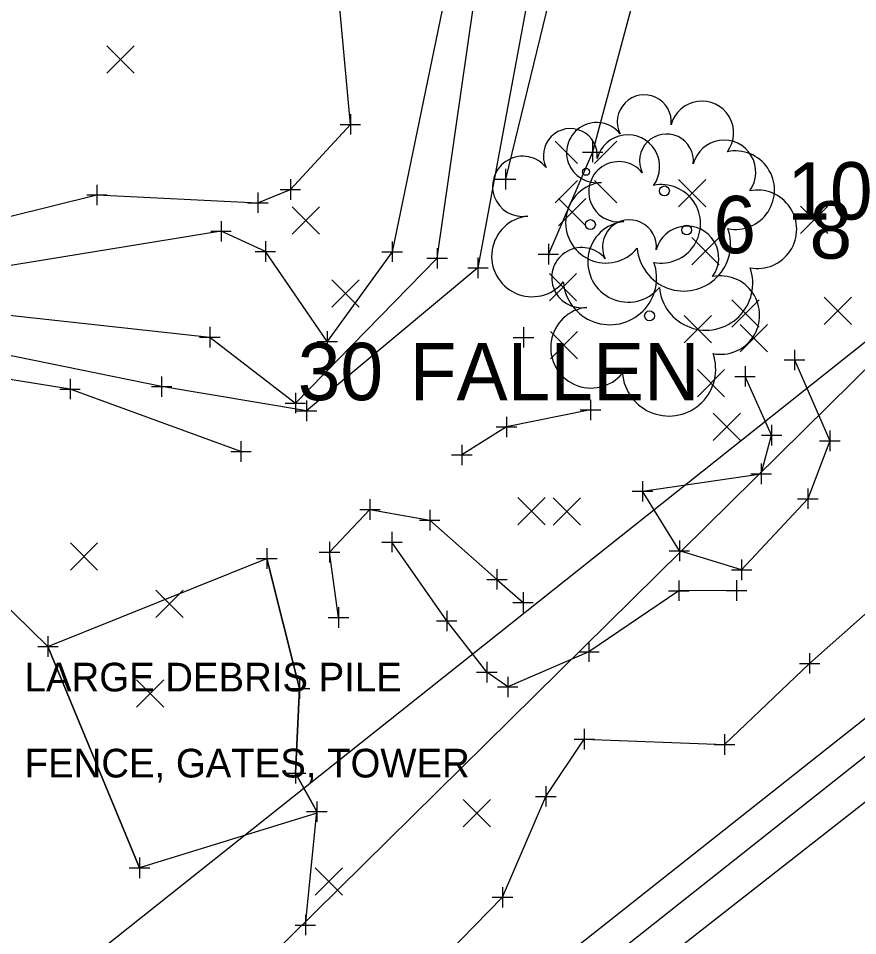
# Model space of a CAD drawing. Extents: x 2184635 to 2185378, y 369880 to 370486.
# Drawn here: x 2184837.78 to 2184878.77, y 370090.62 to 370135.4 of the extents above; entities that cross this region are included whole.
import ezdxf

# ---------------------------------------------------------------- set-up
doc = ezdxf.new("R2010")
doc.units = 0
for name, color, linetype in [('_CIVIL_CONSTRUCTION', 7, 'Continuous'), ('DR_X_Ditch', 7, 'Continuous'), ('GE_X_Alignment', 7, 'Continuous'), ('GE_X_Alignment_100_Distances', 7, 'Continuous'), ('GE_X_Alignment_100_Stations', 7, 'Continuous'), ('PM_X_Edge_Line', 7, 'Continuous'), ('PV_X_EOP', 7, 'Continuous'), ('PV_X_Shoulder', 7, 'Continuous'), ('RD_X_Fence', 7, 'Continuous'), ('RW_X_CL', 7, 'Continuous'), ('RW_X_CL_100_Bearings', 7, 'Continuous'), ('SV_X_Break_Lines', 7, 'Continuous'), ('SV_X_Text', 7, 'Continuous'), ('SV_X_Top_of_Bank', 7, 'Continuous'), ('VG_X_Text', 7, 'Continuous'), ('VG_X_Tree_Line_Lt', 7, 'Continuous')]:
    doc.layers.add(name, color=color, linetype=linetype)

msp = doc.modelspace()

# ---------------------------------------------------------------- linework, layer by layer
at = {"layer": '_CIVIL_CONSTRUCTION'}
for p, q in [((2184842.101, 370132.728), (2184843.434, 370134.063)), ((2184842.101, 370134.063), (2184843.434, 370132.728)), ((2184870.029, 370126.193), (2184871.363, 370127.528)), ((2184870.029, 370127.528), (2184871.363, 370126.193)), ((2184864.166, 370125.274), (2184865.499, 370126.609)), ((2184864.166, 370126.609), (2184865.499, 370125.274)), ((2184851.152, 370124.862), (2184852.486, 370126.198)), ((2184851.152, 370126.198), (2184852.486, 370124.862)), ((2184875.978, 370124.894), (2184877.311, 370126.23)), ((2184875.978, 370126.23), (2184877.311, 370124.894)), ((2184870.672, 370123.36), (2184872.005, 370124.695)), ((2184870.672, 370124.695), (2184872.005, 370123.36)), ((2184853.091, 370121.3), (2184854.424, 370122.635)), ((2184853.091, 370122.635), (2184854.424, 370121.3)), ((2184863.717, 370121.615), (2184865.05, 370122.95)), ((2184863.717, 370122.95), (2184865.05, 370121.615)), ((2184872.633, 370120.328), (2184873.966, 370121.663)), ((2184872.633, 370121.663), (2184873.966, 370120.328)), ((2184877.138, 370120.456), (2184878.472, 370121.791)), ((2184877.138, 370121.791), (2184878.472, 370120.456)), ((2184870.3, 370119.564), (2184871.634, 370120.899)), ((2184870.3, 370120.899), (2184871.634, 370119.564)), ((2184873.032, 370119.116), (2184874.365, 370120.451)), ((2184873.032, 370120.451), (2184874.365, 370119.116)), ((2184863.766, 370118.775), (2184865.099, 370120.11)), ((2184863.766, 370120.11), (2184865.099, 370118.775)), ((2184870.944, 370116.923), (2184872.277, 370118.258)), ((2184870.944, 370118.258), (2184872.277, 370116.923)), ((2184871.72, 370114.791), (2184873.053, 370116.126)), ((2184871.72, 370116.126), (2184873.053, 370114.791)), ((2184862.184, 370110.675), (2184863.517, 370112.01)), ((2184862.184, 370112.01), (2184863.517, 370110.675)), ((2184863.906, 370110.665), (2184865.239, 370112)), ((2184863.906, 370112), (2184865.239, 370110.665)), ((2184840.323, 370108.461), (2184841.657, 370109.796)), ((2184840.323, 370109.796), (2184841.657, 370108.461)), ((2184844.5, 370106.148), (2184845.833, 370107.483)), ((2184844.5, 370107.483), (2184845.833, 370106.148)), ((2184843.558, 370101.779), (2184844.891, 370103.114)), ((2184843.558, 370103.114), (2184844.891, 370101.779)), ((2184859.512, 370095.936), (2184860.845, 370097.271)), ((2184859.512, 370097.271), (2184860.845, 370095.936)), ((2184852.282, 370092.598), (2184853.615, 370093.933)), ((2184852.282, 370093.933), (2184853.615, 370092.598))]:
    msp.add_line(p, q, dxfattribs=at)
at = {"layer": 'DR_X_Ditch'}
msp.add_lwpolyline([(2184772.746, 370158.792), (2184783.456, 370154.562), (2184788.197, 370148.62), (2184793.425, 370146.92), (2184796.855, 370138.137), (2184799.486, 370133.714), (2184806.332, 370123.218), (2184820.592, 370119.162), (2184836.73, 370120.979), (2184847.133, 370119.834), (2184851.315, 370116.623), (2184858.24, 370123.687), (2184860.323, 370138.18), (2184863.22, 370162.438), (2184862.5, 370178.198), (2184848.599, 370182.845), (2184832.556, 370191.984), (2184837.703, 370200.441), (2184846.188, 370203.361)], dxfattribs=at)
at = {"layer": 'GE_X_Alignment'}
for centre in [(2184869.336, 370126.978), (2184865.724, 370125.333), (2184870.42, 370125.068), (2184868.61, 370120.878)]:
    msp.add_circle(centre, 0.24, dxfattribs=at)
for centre, radius, start, end in [((2184868.352, 370130.346), 1.317, 354.0047, 205.9741), ((2184871.162, 370129.808), 1.553, 323.83, 165.0376), ((2184866.027, 370128.843), 1.471, 39.0625, 279.5412), ((2184864.74, 370128.701), 1.317, 354.0047, 205.9741), ((2184867.55, 370128.162), 1.553, 323.83, 165.0376), ((2184869.436, 370128.436), 1.317, 354.0047, 205.9741), ((2184872.246, 370127.898), 1.553, 323.83, 165.0376), ((2184872.796, 370127.014), 1.915, 259.1453, 101.4596), ((2184862.415, 370127.197), 1.471, 39.0625, 279.5412), ((2184867.11, 370126.933), 1.471, 39.0625, 279.5412), ((2184866.483, 370125.43), 1.974, 96.1722, 320.5737), ((2184869.184, 370125.369), 1.915, 259.1453, 101.4596), ((2184873.88, 370125.104), 1.915, 259.1453, 101.4596), ((2184862.871, 370123.784), 1.974, 96.1722, 320.5737), ((2184867.566, 370123.52), 1.974, 96.1722, 320.5737), ((2184867.627, 370124.245), 1.317, 354.0047, 205.9741), ((2184870.436, 370123.707), 1.553, 323.83, 165.0376), ((2184870.282, 370124.373), 2.284, 184.9476, 19.4572), ((2184865.301, 370122.742), 1.471, 39.0625, 279.5412), ((2184866.671, 370122.728), 2.284, 184.9476, 19.4572), ((2184871.366, 370122.463), 2.284, 184.9476, 19.4572), ((2184872.071, 370120.914), 1.915, 259.1453, 101.4596), ((2184865.757, 370119.329), 1.974, 96.1722, 320.5737), ((2184869.557, 370118.273), 2.284, 184.9476, 19.4572)]:
    msp.add_arc(centre, radius, start, end, dxfattribs=at)
at = {"layer": 'GE_X_Alignment_100_Distances'}
msp.add_lwpolyline([(2184659.612, 369925.949), (2184700.373, 369957.788), (2184738.497, 369988.629), (2184777.827, 370020.252), (2184816.427, 370051.346), (2184855.546, 370082.582), (2184897.005, 370115.363), (2184935.605, 370145.229), (2184944.916, 370153.839), (2184957.869, 370164.566), (2184961.936, 370169.284), (2184974.725, 370179.722), (2184983.893, 370187.218), (2184992.505, 370194.662), (2184997.566, 370200.246)], dxfattribs=at)
at = {"layer": 'GE_X_Alignment_100_Stations'}
for p, q in [((2184863.997, 370129.412), (2184865.09, 370128.318)), ((2184865.923, 370128.318), (2184867.015, 370129.412)), ((2184863.997, 370126.393), (2184865.09, 370127.487)), ((2184865.923, 370127.487), (2184867.015, 370126.393))]:
    msp.add_line(p, q, dxfattribs=at)
msp.add_circle((2184865.507, 370127.908), 0.17, dxfattribs=at)
at = {"layer": 'PM_X_Edge_Line'}
msp.add_lwpolyline([(2184661.525, 369922.948), (2184702.122, 369955.424), (2184740.459, 369986.306), (2184779.792, 370018.036), (2184818.421, 370048.832), (2184857.458, 370080.192), (2184899.139, 370112.801), (2184937.357, 370142.735), (2184976.78, 370173.64), (2185013.226, 370203.926), (2185054.743, 370235.213), (2185093.131, 370266.204), (2185132.902, 370298.208), (2185170.876, 370328.987), (2185209.713, 370360.437), (2185248.243, 370392.049)], dxfattribs=at)
at = {"layer": 'PV_X_EOP'}
msp.add_lwpolyline([(2184661.562, 369922.858), (2184702.122, 369955.424), (2184740.459, 369986.306), (2184779.792, 370018.036), (2184818.421, 370048.832), (2184857.458, 370080.192), (2184899.139, 370112.801), (2184937.357, 370142.735), (2184976.78, 370173.64), (2185013.226, 370203.926), (2185054.743, 370235.213), (2185093.131, 370266.204), (2185132.902, 370298.208), (2185170.876, 370328.987), (2185209.713, 370360.437), (2185248.181, 370392.045)], dxfattribs=at)
at = {"layer": 'PV_X_Shoulder'}
msp.add_lwpolyline([(2184660.616, 369924.653), (2184701.177, 369956.993), (2184739.308, 369987.689), (2184778.66, 370019.08), (2184817.145, 370050.202), (2184856.424, 370081.402), (2184897.962, 370114.276), (2184936.317, 370143.726), (2184975.811, 370174.815), (2184986.608, 370184.308), (2184994.082, 370192.548), (2185011.043, 370206.648), (2185033.171, 370224.287), (2185051.814, 370238.9), (2185062.885, 370246.964), (2185064.956, 370248.001), (2185067.328, 370248.113), (2185092.06, 370267.243), (2185132.002, 370299.513), (2185169.971, 370330.255), (2185208.837, 370361.607), (2185247.242, 370392.983)], dxfattribs=at)
at = {"layer": 'RD_X_Fence'}
msp.add_lwpolyline([(2184709.157, 369984.536), (2184726.864, 369998.781), (2184769.898, 370032.731), (2184797.39, 370054.67), (2184814.475, 370067.872), (2184833.193, 370083.116), (2184887.166, 370125.991), (2184905.933, 370138.502)], dxfattribs=at)
at = {"layer": 'RW_X_CL'}
for p, q in [((2184853.998, 370130.725), (2184853.998, 370129.725)), ((2184853.498, 370130.225), (2184854.498, 370130.225)), ((2184853.998, 370130.225), (2184853.998, 370130.225)), ((2184865.827, 370129.373), (2184865.827, 370128.373)), ((2184865.327, 370128.873), (2184866.327, 370128.873)), ((2184865.827, 370128.873), (2184865.827, 370128.873)), ((2184861.572, 370128.049), (2184861.572, 370127.049)), ((2184851.069, 370127.542), (2184851.069, 370126.542)), ((2184861.072, 370127.549), (2184862.072, 370127.549)), ((2184861.572, 370127.549), (2184861.572, 370127.549)), ((2184841.621, 370127.277), (2184841.621, 370126.277)), ((2184850.569, 370127.042), (2184851.569, 370127.042)), ((2184851.069, 370127.042), (2184851.069, 370127.042)), ((2184841.121, 370126.777), (2184842.121, 370126.777)), ((2184841.621, 370126.777), (2184841.621, 370126.777)), ((2184849.477, 370126.9), (2184849.477, 370125.9)), ((2184848.977, 370126.4), (2184849.977, 370126.4)), ((2184849.477, 370126.4), (2184849.477, 370126.4)), ((2184847.684, 370125.507), (2184847.684, 370124.507)), ((2184847.184, 370125.007), (2184848.184, 370125.007)), ((2184847.684, 370125.007), (2184847.684, 370125.007)), ((2184849.85, 370124.516), (2184849.85, 370123.516)), ((2184856.041, 370124.509), (2184856.041, 370123.509)), ((2184863.667, 370124.388), (2184863.667, 370123.388)), ((2184849.35, 370124.016), (2184850.35, 370124.016)), ((2184849.85, 370124.016), (2184849.85, 370124.016)), ((2184855.541, 370124.009), (2184856.541, 370124.009)), ((2184856.041, 370124.009), (2184856.041, 370124.009)), ((2184858.24, 370124.187), (2184858.24, 370123.187)), ((2184863.167, 370123.888), (2184864.167, 370123.888)), ((2184863.667, 370123.888), (2184863.667, 370123.888)), ((2184857.74, 370123.687), (2184858.74, 370123.687)), ((2184858.24, 370123.687), (2184858.24, 370123.687)), ((2184860.23, 370123.719), (2184860.23, 370122.719)), ((2184859.73, 370123.219), (2184860.73, 370123.219)), ((2184860.23, 370123.219), (2184860.23, 370123.219)), ((2184847.133, 370120.334), (2184847.133, 370119.334)), ((2184846.633, 370119.834), (2184847.633, 370119.834)), ((2184847.133, 370119.834), (2184847.133, 370119.834)), ((2184852.867, 370120.123), (2184852.867, 370119.123)), ((2184852.367, 370119.623), (2184853.367, 370119.623)), ((2184852.867, 370119.623), (2184852.867, 370119.623)), ((2184875.687, 370119.225), (2184875.687, 370118.225)), ((2184875.187, 370118.725), (2184876.187, 370118.725)), ((2184875.687, 370118.725), (2184875.687, 370118.725)), ((2184873.272, 370118.424), (2184873.272, 370117.424)), ((2184840.308, 370117.804), (2184840.308, 370116.804)), ((2184844.781, 370117.925), (2184844.781, 370116.925)), ((2184872.772, 370117.924), (2184873.772, 370117.924)), ((2184873.272, 370117.924), (2184873.272, 370117.924)), ((2184839.808, 370117.304), (2184840.808, 370117.304)), ((2184840.308, 370117.304), (2184840.308, 370117.304)), ((2184844.281, 370117.425), (2184845.281, 370117.425)), ((2184844.781, 370117.425), (2184844.781, 370117.425)), ((2184851.315, 370117.123), (2184851.315, 370116.123)), ((2184851.862, 370116.742), (2184851.862, 370115.742)), ((2184865.724, 370116.786), (2184865.724, 370115.786)), ((2184850.815, 370116.623), (2184851.815, 370116.623)), ((2184851.315, 370116.623), (2184851.315, 370116.623)), ((2184865.224, 370116.286), (2184866.224, 370116.286)), ((2184865.724, 370116.286), (2184865.724, 370116.286)), ((2184851.362, 370116.242), (2184852.362, 370116.242)), ((2184851.862, 370116.242), (2184851.862, 370116.242)), ((2184861.621, 370115.953), (2184861.621, 370114.953)), ((2184861.121, 370115.453), (2184862.121, 370115.453)), ((2184861.621, 370115.453), (2184861.621, 370115.453)), ((2184874.571, 370115.551), (2184874.571, 370114.551)), ((2184874.071, 370115.051), (2184875.071, 370115.051)), ((2184874.571, 370115.051), (2184874.571, 370115.051)), ((2184877.417, 370115.279), (2184877.417, 370114.279)), ((2184848.656, 370114.757), (2184848.656, 370113.757)), ((2184859.439, 370114.586), (2184859.439, 370113.586)), ((2184876.917, 370114.779), (2184877.917, 370114.779)), ((2184877.417, 370114.779), (2184877.417, 370114.779)), ((2184848.156, 370114.257), (2184849.156, 370114.257)), ((2184848.656, 370114.257), (2184848.656, 370114.257)), ((2184858.939, 370114.086), (2184859.939, 370114.086)), ((2184859.439, 370114.086), (2184859.439, 370114.086)), ((2184874.058, 370113.667), (2184874.058, 370112.667)), ((2184873.558, 370113.167), (2184874.558, 370113.167)), ((2184874.058, 370113.167), (2184874.058, 370113.167)), ((2184868.266, 370112.816), (2184868.266, 370111.816)), ((2184867.766, 370112.316), (2184868.766, 370112.316)), ((2184868.266, 370112.316), (2184868.266, 370112.316)), ((2184876.339, 370112.45), (2184876.339, 370111.45)), ((2184854.953, 370111.922), (2184854.953, 370110.922)), ((2184875.839, 370111.95), (2184876.839, 370111.95)), ((2184876.339, 370111.95), (2184876.339, 370111.95)), ((2184854.453, 370111.422), (2184855.453, 370111.422)), ((2184854.953, 370111.422), (2184854.953, 370111.422)), ((2184857.873, 370111.406), (2184857.873, 370110.406)), ((2184857.373, 370110.906), (2184858.373, 370110.906)), ((2184857.873, 370110.906), (2184857.873, 370110.906)), ((2184856.029, 370110.335), (2184856.029, 370109.335)), ((2184849.922, 370109.535), (2184849.922, 370108.535)), ((2184852.978, 370109.84), (2184852.978, 370108.84)), ((2184855.529, 370109.835), (2184856.529, 370109.835)), ((2184856.029, 370109.835), (2184856.029, 370109.835)), ((2184870.068, 370109.911), (2184870.068, 370108.911)), ((2184852.478, 370109.34), (2184853.478, 370109.34)), ((2184852.978, 370109.34), (2184852.978, 370109.34)), ((2184869.568, 370109.411), (2184870.568, 370109.411)), ((2184870.068, 370109.411), (2184870.068, 370109.411)), ((2184849.422, 370109.035), (2184850.422, 370109.035)), ((2184849.922, 370109.035), (2184849.922, 370109.035)), ((2184873.106, 370108.979), (2184873.106, 370107.979)), ((2184861.159, 370108.516), (2184861.159, 370107.516)), ((2184872.606, 370108.479), (2184873.606, 370108.479)), ((2184873.106, 370108.479), (2184873.106, 370108.479)), ((2184860.659, 370108.016), (2184861.659, 370108.016)), ((2184861.159, 370108.016), (2184861.159, 370108.016)), ((2184870.037, 370107.96), (2184870.037, 370106.96)), ((2184872.853, 370107.969), (2184872.853, 370106.969)), ((2184862.43, 370107.393), (2184862.43, 370106.393)), ((2184869.537, 370107.46), (2184870.537, 370107.46)), ((2184870.037, 370107.46), (2184870.037, 370107.46)), ((2184872.353, 370107.469), (2184873.353, 370107.469)), ((2184872.853, 370107.469), (2184872.853, 370107.469)), ((2184861.93, 370106.893), (2184862.93, 370106.893)), ((2184862.43, 370106.893), (2184862.43, 370106.893)), ((2184853.422, 370106.653), (2184853.422, 370105.653)), ((2184858.702, 370106.483), (2184858.702, 370105.483)), ((2184852.922, 370106.153), (2184853.922, 370106.153)), ((2184853.422, 370106.153), (2184853.422, 370106.153)), ((2184858.202, 370105.983), (2184859.202, 370105.983)), ((2184858.702, 370105.983), (2184858.702, 370105.983)), ((2184839.229, 370105.236), (2184839.229, 370104.236)), ((2184838.729, 370104.736), (2184839.729, 370104.736)), ((2184839.229, 370104.736), (2184839.229, 370104.736)), ((2184865.649, 370104.986), (2184865.649, 370103.986)), ((2184865.149, 370104.486), (2184866.149, 370104.486)), ((2184865.649, 370104.486), (2184865.649, 370104.486)), ((2184876.425, 370104.416), (2184876.425, 370103.416)), ((2184860.662, 370103.988), (2184860.662, 370102.988)), ((2184875.925, 370103.916), (2184876.925, 370103.916)), ((2184876.425, 370103.916), (2184876.425, 370103.916)), ((2184860.162, 370103.488), (2184861.162, 370103.488)), ((2184860.662, 370103.488), (2184860.662, 370103.488)), ((2184861.685, 370103.265), (2184861.685, 370102.265)), ((2184851.513, 370103.191), (2184851.513, 370102.191)), ((2184851.013, 370102.691), (2184852.013, 370102.691)), ((2184851.513, 370102.691), (2184851.513, 370102.691)), ((2184861.185, 370102.765), (2184862.185, 370102.765)), ((2184861.685, 370102.765), (2184861.685, 370102.765)), ((2184865.421, 370100.714), (2184865.421, 370099.714)), ((2184864.921, 370100.214), (2184865.921, 370100.214)), ((2184865.421, 370100.214), (2184865.421, 370100.214)), ((2184872.27, 370100.455), (2184872.27, 370099.455)), ((2184871.77, 370099.955), (2184872.77, 370099.955)), ((2184872.27, 370099.955), (2184872.27, 370099.955)), ((2184851.32, 370099.058), (2184851.32, 370098.058)), ((2184850.82, 370098.558), (2184851.82, 370098.558)), ((2184851.32, 370098.558), (2184851.32, 370098.558)), ((2184863.541, 370097.923), (2184863.541, 370096.923)), ((2184852.364, 370097.18), (2184852.364, 370096.18)), ((2184863.041, 370097.423), (2184864.041, 370097.423)), ((2184863.541, 370097.423), (2184863.541, 370097.423)), ((2184851.864, 370096.68), (2184852.864, 370096.68)), ((2184852.364, 370096.68), (2184852.364, 370096.68)), ((2184843.697, 370094.437), (2184843.697, 370093.437)), ((2184843.197, 370093.937), (2184844.197, 370093.937)), ((2184843.697, 370093.937), (2184843.697, 370093.937)), ((2184861.427, 370092.997), (2184861.427, 370091.997)), ((2184860.927, 370092.497), (2184861.927, 370092.497)), ((2184861.427, 370092.497), (2184861.427, 370092.497)), ((2184851.8, 370091.641), (2184851.8, 370090.641)), ((2184851.3, 370091.141), (2184852.3, 370091.141)), ((2184851.8, 370091.141), (2184851.8, 370091.141))]:
    msp.add_line(p, q, dxfattribs=at)
at = {"layer": 'RW_X_CL_100_Bearings'}
for p, q in [((2184862.453, 370120.325), (2184862.453, 370119.325)), ((2184861.953, 370119.825), (2184862.953, 370119.825)), ((2184862.453, 370119.825), (2184862.453, 370119.825))]:
    msp.add_line(p, q, dxfattribs=at)
at = {"layer": 'SV_X_Break_Lines'}
for points in [[(2184847.446, 370201.078), (2184834.811, 370193.51), (2184845.709, 370185.722), (2184859.639, 370184.834), (2184862.388, 370180.309), (2184865.693, 370171.126), (2184865.101, 370155.292), (2184863.901, 370143.074), (2184860.23, 370123.219), (2184851.862, 370116.242), (2184844.781, 370117.425), (2184833.754, 370119.669), (2184824.168, 370118.001), (2184814.096, 370116.756), (2184804.566, 370122.841), (2184797.93, 370133.989), (2184788.336, 370145.101), (2184776.293, 370154.453)], [(2184828.544, 370123.552), (2184841.621, 370126.777), (2184849.477, 370126.4), (2184851.069, 370127.042), (2184853.998, 370130.225), (2184853.364, 370137.147), (2184854.398, 370149.727), (2184851.447, 370163.465), (2184848.991, 370176.215), (2184835.789, 370182.952)], [(2184855.682, 370179.835), (2184858.538, 370176.245), (2184861.311, 370161.04), (2184860.114, 370143.698), (2184856.041, 370124.009), (2184852.867, 370119.623), (2184849.85, 370124.016), (2184847.684, 370125.007), (2184832.207, 370122.487)], [(2184892.741, 370178.112), (2184880.94, 370163.287), (2184878.623, 370154.331), (2184870.304, 370148.648), (2184868.943, 370140.53), (2184865.827, 370128.873), (2184863.667, 370123.888)], [(2184875.687, 370118.725), (2184877.417, 370114.779), (2184876.339, 370111.95), (2184873.106, 370108.479), (2184870.068, 370109.411), (2184868.266, 370112.316), (2184874.058, 370113.167), (2184874.571, 370115.051), (2184873.272, 370117.924)], [(2184865.724, 370116.286), (2184861.621, 370115.453), (2184859.439, 370114.086)], [(2184815.75, 370115.532), (2184832.476, 370111.334), (2184839.229, 370104.736), (2184843.697, 370093.937)], [(2184853.422, 370106.153), (2184852.978, 370109.34), (2184854.953, 370111.422), (2184857.873, 370110.906), (2184861.159, 370108.016), (2184862.43, 370106.893)], [(2184872.853, 370107.469), (2184870.037, 370107.46), (2184865.649, 370104.486), (2184861.685, 370102.765), (2184860.662, 370103.488), (2184858.702, 370105.983), (2184856.029, 370109.835)], [(2184851.8, 370091.141), (2184852.364, 370096.68), (2184851.32, 370098.558), (2184851.513, 370102.691), (2184849.922, 370109.035)]]:
    msp.add_lwpolyline(points, dxfattribs=at)
at = {"layer": 'SV_X_Text'}
msp.add_lwpolyline([(2184852.357, 370096.608), (2184843.697, 370093.937), (2184839.229, 370104.736), (2184849.922, 370109.035), (2184851.513, 370102.691), (2184851.32, 370098.558), (2184852.364, 370096.68)], dxfattribs=at)
at = {"layer": 'SV_X_Top_of_Bank'}
for points in [[(2184848.333, 370199.868), (2184841.014, 370194.314), (2184843.015, 370190.526), (2184848.448, 370188.396), (2184860.708, 370186.136), (2184865.589, 370183.475), (2184868.19, 370171.911), (2184865.546, 370159.118), (2184865.671, 370144.411), (2184861.572, 370127.549)], [(2184834.448, 370083.78), (2184836.257, 370081.529), (2184839.923, 370080.988), (2184844.893, 370084.573), (2184850.319, 370082.147), (2184853.958, 370083.162), (2184857.342, 370086.266), (2184858.074, 370089.072), (2184861.427, 370092.497), (2184863.541, 370097.423), (2184865.421, 370100.214), (2184872.27, 370099.955), (2184876.425, 370103.916), (2184881.307, 370108.241), (2184882.469, 370112.922), (2184883.938, 370117.722), (2184887.117, 370120.048)], [(2184848.656, 370114.257), (2184840.308, 370117.304), (2184833.817, 370118.338), (2184827.893, 370118.566)]]:
    msp.add_lwpolyline(points, dxfattribs=at)
at = {"layer": 'VG_X_Tree_Line_Lt'}
msp.add_lwpolyline([(2185010.677, 370261.152), (2185009.496, 370230.83), (2184994.447, 370214.873), (2184919.447, 370148.63), (2184883.31, 370122.364), (2184845.078, 370084.673), (2184789.476, 370110.598), (2184762.675, 370135.815)], dxfattribs=at)

# ---------------------------------------------------------------- texts
at = {"layer": 'SV_X_Text'}
for s, p in [('LARGE DEBRIS PILE', (2184838.092, 370102.545)), ('FENCE, GATES, TOWER', (2184838.092, 370098.345))]:
    msp.add_text(s, height=1.4, dxfattribs=at).set_placement(p)
at = {"layer": 'VG_X_Text'}
for s, p in [('10', (2184875.336, 370125.579)), ('6', (2184871.724, 370123.933)), ('8', (2184876.42, 370123.668)), ('30', (2184851.431, 370116.759)), ('FALLEN', (2184856.897, 370116.759))]:
    msp.add_text(s, height=2.8, dxfattribs=at).set_placement(p)

doc.saveas('drawing.dxf')
